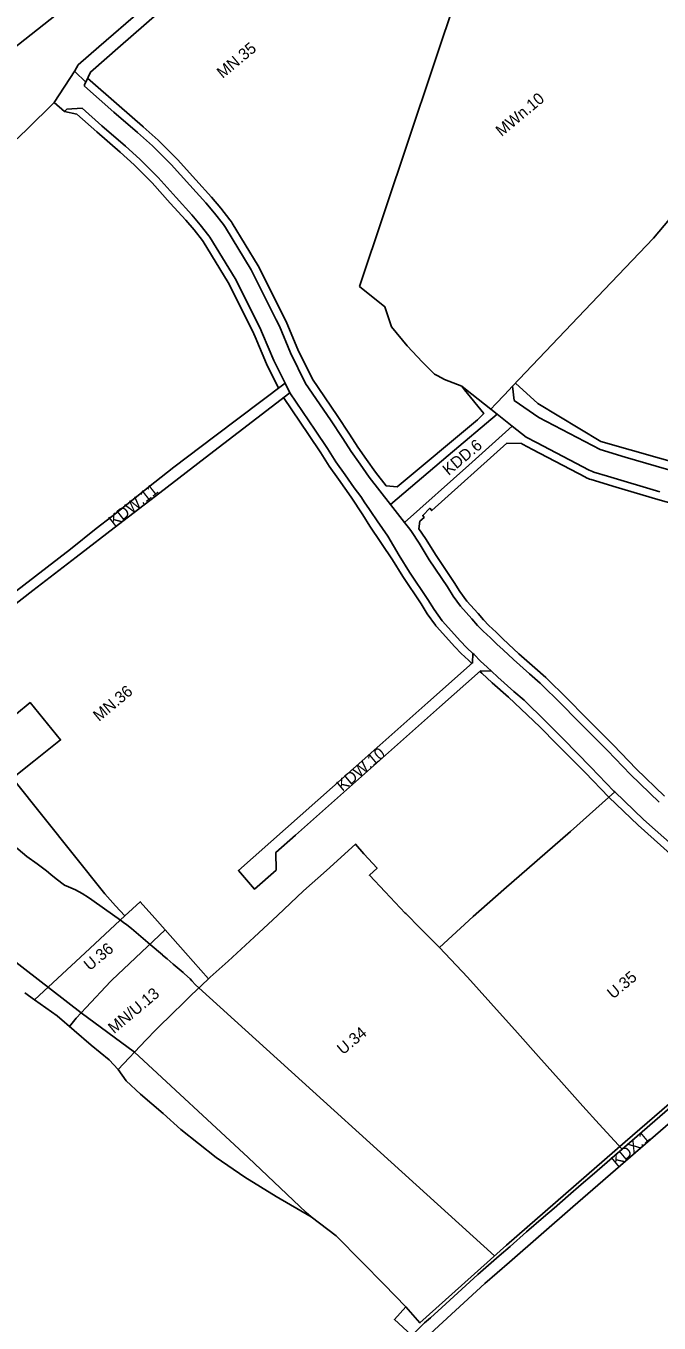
# Model space of a CAD drawing. Extents: x 7418616 to 7420822, y 5550745 to 5553106.
# Drawn here: x 7419277 to 7419553, y 5551619 to 5552185 of the extents above; entities that cross this region are included whole.
import ezdxf

# ---------------------------------------------------------------- set-up
doc = ezdxf.new("R2010")
doc.units = 0
for name, color, linetype in [('granica obszaru objętego planem', 7, 'Continuous'), ('granica strefy zwiększonej wysokości zabudowy', 7, 'Continuous'), ('linie rozgraniczające', 7, 'Continuous'), ('nieprzekraczalne linie zabudowy', 7, 'Continuous'), ('przeznaczenia terenów', 7, 'Continuous')]:
    doc.layers.add(name, color=color, linetype=linetype)

msp = doc.modelspace()

# ---------------------------------------------------------------- linework, layer by layer
at = {"layer": 'granica obszaru objętego planem'}
msp.add_lwpolyline([(7419449.2, 5551610.35), (7419437.9, 5551620.76), (7419442.91, 5551626.23), (7419433.45, 5551635.98), (7419423.64, 5551645.92), (7419412.45, 5551657.3), (7419401.59, 5551665.49), (7419386.37, 5551674.34), (7419372.7, 5551682.86), (7419360.17, 5551691.36), (7419344.8, 5551703.65), (7419337.04, 5551710.52), (7419327.19, 5551719.01), (7419320.85, 5551724.84), (7419317.35, 5551729.81), (7419313.4, 5551733.94), (7419305.54, 5551740.35), (7419290.8, 5551753.13), (7419285.81, 5551756.69), (7419280.87, 5551760.17), (7419276.65, 5551763.24)], dxfattribs=at)
at = {"layer": 'granica strefy zwiększonej wysokości zabudowy'}
for points in [[(7419269.08, 5551829.76), (7419277.58, 5551822.71), (7419282, 5551819.44), (7419282.05, 5551819.4), (7419284.9, 5551817.28), (7419285.5, 5551816.83), (7419286.11, 5551816.35), (7419288.07, 5551814.8), (7419290.39, 5551812.96), (7419293.92, 5551810.16), (7419295.78, 5551809.43), (7419298.76, 5551808.08), (7419301.65, 5551806.54), (7419304.43, 5551804.81), (7419305.93, 5551803.77), (7419311.44, 5551799.79), (7419318.36, 5551794.88), (7419319.73, 5551793.91), (7419321.24, 5551792.8), (7419323.15, 5551791.25), (7419331.29, 5551784.35), (7419336.75, 5551779.72), (7419336.78, 5551779.69), (7419338.71, 5551778.05), (7419341.46, 5551775.71), (7419345.78, 5551772.04), (7419346.37, 5551771.53), (7419348.76, 5551769.3), (7419349.53, 5551768.5), (7419351.2, 5551766.76), (7419352.58, 5551765.32)], [(7419352.6, 5551765.34), (7419481.58, 5551648.48)]]:
    msp.add_lwpolyline(points, dxfattribs=at)
at = {"layer": 'linie rozgraniczające'}
for p, q in [((7419289.46, 5552151.49), (7419298.49, 5552165.33)), ((7419298.49, 5552165.33), (7419298.49, 5552165.08)), ((7419298.49, 5552165.08), (7419303.22, 5552160.41)), ((7419392.25, 5552024.94), (7419390.21, 5552029.04)), ((7419480.03, 5552017.75), (7419471.68, 5552024.34)), ((7419482.73, 5552015.61), (7419480.03, 5552017.75)), ((7419489.32, 5552010.39), (7419482.73, 5552015.61)), ((7419436.19, 5551976.2), (7419442.37, 5551968.29))]:
    msp.add_line(p, q, dxfattribs=at)
for points in [[(7419365.97, 5552250.04), (7419312.1, 5552206.93), (7419296.89, 5552194.85), (7419293.29, 5552192.01), (7419273.97, 5552176.76), (7419270.76, 5552174.26), (7419254.96, 5552161.91), (7419239.68, 5552149.67), (7419236.93, 5552147.47)], [(7419471.68, 5552024.34), (7419469.73, 5552025.85), (7419467.37, 5552027.79), (7419459.79, 5552030.67), (7419456.81, 5552032.24), (7419455.37, 5552033), (7419450.17, 5552038.3), (7419443.52, 5552045.43), (7419436.66, 5552053.6), (7419433.69, 5552062.45), (7419422.76, 5552071.31), (7419476.4, 5552231.68)], [(7419298.49, 5552165.33), (7419299.92, 5552167.9), (7419308.97, 5552175.78), (7419327.07, 5552191.53), (7419345.17, 5552207.3), (7419367.41, 5552226.67), (7419372.62, 5552223.69), (7419353.06, 5552206.57), (7419336.88, 5552192.4), (7419334.25, 5552190.1), (7419318.45, 5552176.27), (7419305.31, 5552164.76), (7419303.22, 5552160.41)], [(7419489.5, 5552027.77), (7419532.5, 5552072.94), (7419550.98, 5552092.35), (7419557.99, 5552100.66), (7419563.48, 5552108.39), (7419565.89, 5552112.66), (7419568.3, 5552117.09), (7419571.58, 5552124.75), (7419588.49, 5552168.69), (7419594.7, 5552185.4), (7419598.11, 5552195.09), (7419599.69, 5552199.82), (7419601.92, 5552206.93), (7419603.31, 5552211.68), (7419604.21, 5552214.8), (7419606.15, 5552222.19)], [(7419303.22, 5552160.41), (7419302.74, 5552159.41), (7419302.72, 5552158.67), (7419315.57, 5552147.36), (7419325.89, 5552138.49), (7419332.37, 5552132.57), (7419340.5, 5552124.44), (7419348.62, 5552115.4), (7419355.63, 5552107.75), (7419359.42, 5552103.21), (7419363.36, 5552098.23), (7419363.9, 5552097.48), (7419364.23, 5552096.97), (7419375.39, 5552078.6), (7419386.4, 5552056.77), (7419387.74, 5552053.89), (7419392.54, 5552042.3), (7419399.15, 5552029.02), (7419410.07, 5552013.09), (7419415.42, 5552004.92), (7419419, 5551999.29), (7419422.94, 5551993.81), (7419426.86, 5551988.16), (7419436.19, 5551976.2)], [(7419238.99, 5552145.43), (7419260.69, 5552123.96), (7419263.29, 5552126.31), (7419277.6, 5552139.69), (7419289.46, 5552151.49)], [(7419390.21, 5552029.04), (7419385.26, 5552038.98), (7419380.42, 5552050.67), (7419379.15, 5552053.39), (7419368.39, 5552074.71), (7419357.39, 5552092.82), (7419356.96, 5552093.42), (7419353.16, 5552098.22), (7419349.53, 5552102.58), (7419342.69, 5552110.03), (7419334.81, 5552118.81), (7419326.8, 5552126.83), (7419320.55, 5552132.53), (7419310.32, 5552141.32), (7419301.61, 5552149), (7419295.06, 5552148.62), (7419293.97, 5552147.53), (7419289.46, 5552151.49)], [(7419200.17, 5551882.67), (7419214.91, 5551893.91), (7419222.45, 5551899.78), (7419230.97, 5551906.24), (7419240.24, 5551913.47), (7419271.1, 5551937.05), (7419296.59, 5551956.64), (7419307.85, 5551965.65), (7419314.56, 5551971.02), (7419333.41, 5551985.96), (7419341.61, 5551992.46), (7419359.62, 5552006.02), (7419390.21, 5552029.04)], [(7419392.25, 5552024.94), (7419355.37, 5551996.55), (7419335.6, 5551981.33), (7419317.5, 5551967.39), (7419299.12, 5551953.24), (7419280.13, 5551938.61), (7419261.43, 5551924.21), (7419242.4, 5551909.56), (7419223.6, 5551895.08), (7419204.9, 5551880.69)], [(7419472.13, 5551911.27), (7419469.48, 5551913.7), (7419466.63, 5551916.66), (7419464.13, 5551919.52), (7419461.44, 5551922.48), (7419458.95, 5551925.24), (7419458.74, 5551925.5), (7419455.2, 5551930.43), (7419452.54, 5551934.69), (7419444.53, 5551946.62), (7419440.05, 5551953.87), (7419435.04, 5551962.43), (7419430.47, 5551969.02), (7419427.59, 5551973.14), (7419426.76, 5551974.41), (7419424.95, 5551976.92), (7419423.25, 5551979.67), (7419420.41, 5551983.43), (7419416.41, 5551989.19), (7419412.36, 5551994.82), (7419408.7, 5552000.58), (7419403.42, 5552008.64), (7419392.25, 5552024.94)], [(7419480.03, 5552017.75), (7419482.18, 5552020.07), (7419485.97, 5552024.06), (7419489.5, 5552027.77)], [(7419489.5, 5552027.77), (7419490.15, 5552021.57), (7419500.93, 5552014.06), (7419527.68, 5552000.16), (7419538.61, 5551996.88), (7419556.58, 5551991.54), (7419573.63, 5551986.81), (7419587.72, 5551983.01), (7419590.08, 5551982.51)], [(7419436.19, 5551976.2), (7419461.43, 5551997.57), (7419482.73, 5552015.61)], [(7419442.37, 5551968.29), (7419470.33, 5551993.36), (7419489.32, 5552010.39)], [(7419553.71, 5551981.75), (7419530.83, 5551988.56), (7419524.89, 5551990.35), (7419524.41, 5551990.53), (7419522.87, 5551991.2), (7419499.89, 5552003.24), (7419495.42, 5552005.6), (7419489.32, 5552010.39)], [(7419442.37, 5551968.29), (7419444.6, 5551965.43), (7419445.34, 5551964.34), (7419448.69, 5551959.3), (7419453.15, 5551952.07), (7419461.06, 5551940.31), (7419463.59, 5551936.23), (7419466.76, 5551931.81), (7419471.77, 5551926.28), (7419474.22, 5551923.48), (7419476.64, 5551920.97), (7419479.86, 5551918.03), (7419482.6, 5551915.2), (7419485.31, 5551912.75), (7419489.89, 5551908.52), (7419496.8, 5551902.33), (7419501.49, 5551898.2), (7419510.98, 5551888.98), (7419517.4, 5551882.48), (7419530.93, 5551868.85), (7419540.95, 5551858.38), (7419553.46, 5551846.41)], [(7419480.24, 5551903.55), (7419475.46, 5551903.57), (7419457.63, 5551887.76), (7419436.68, 5551869.19), (7419415.73, 5551850.61), (7419394.77, 5551832.04), (7419386.2, 5551824.44), (7419386.32, 5551816.77), (7419376.91, 5551808.42), (7419375.11, 5551810.48), (7419369.85, 5551816.5), (7419390.43, 5551834.74), (7419410.96, 5551852.94), (7419431.58, 5551871.22), (7419452.54, 5551889.8), (7419472.04, 5551907.08), (7419472.13, 5551911.27)], [(7419480.24, 5551903.55), (7419478.41, 5551905.23), (7419475.44, 5551907.92), (7419472.69, 5551910.76), (7419472.13, 5551911.27)], [(7419534.03, 5551850.88), (7419533.73, 5551851.17), (7419523.66, 5551861.7), (7419511.49, 5551873.96), (7419503.86, 5551881.7), (7419494.47, 5551890.79), (7419490.05, 5551894.68), (7419483.05, 5551900.95), (7419480.24, 5551903.55)], [(7419213.04, 5551869.32), (7419226.26, 5551879.01), (7419232.46, 5551883.78), (7419233.36, 5551882.9), (7419247.56, 5551864.17), (7419258.46, 5551872.91), (7419265.33, 5551878.57), (7419267.03, 5551879.97), (7419278.98, 5551889.81), (7419292.23, 5551873.48), (7419280.64, 5551864.29), (7419271.31, 5551856.81), (7419311.51, 5551806.43), (7419316.29, 5551801.08), (7419320.36, 5551796.74)], [(7419457.55, 5551782.96), (7419472.35, 5551796.53), (7419485.69, 5551808.21), (7419514.83, 5551833.6), (7419534.03, 5551850.88)], [(7419623.53, 5551770), (7419619.37, 5551773.85), (7419615.55, 5551777.67), (7419609.66, 5551783.38), (7419598.83, 5551793.4), (7419589.26, 5551801.63), (7419576.19, 5551812.52), (7419571.18, 5551816.89), (7419560.52, 5551826.38), (7419546.59, 5551838.86), (7419534.03, 5551850.88)], [(7419356.86, 5551769.32), (7419357.56, 5551769.98), (7419365.32, 5551777.02), (7419376.72, 5551787.51), (7419378.74, 5551789.4), (7419386.89, 5551797), (7419398.3, 5551807.65), (7419408.24, 5551816.63), (7419420.89, 5551828.06), (7419424.63, 5551823.9), (7419430.36, 5551817.54), (7419427.02, 5551814.5), (7419433.9, 5551807.26), (7419442.68, 5551798.01), (7419442.91, 5551797.76), (7419449.2, 5551791.41), (7419457.55, 5551782.96)], [(7419320.36, 5551796.74), (7419327.06, 5551802.94), (7419333.39, 5551795.8), (7419337.97, 5551790.63)], [(7419320.36, 5551796.74), (7419303.01, 5551780.68), (7419280.87, 5551760.17)], [(7419337.97, 5551790.63), (7419314.65, 5551768.72), (7419314.11, 5551768.16), (7419303.44, 5551756.85), (7419299.1, 5551752.11), (7419296.16, 5551748.48)], [(7419337.97, 5551790.63), (7419346.77, 5551780.71), (7419356.86, 5551769.32)], [(7419457.55, 5551782.96), (7419469.78, 5551770.09), (7419480.06, 5551758.64), (7419491.62, 5551745.76), (7419500.82, 5551735.51), (7419510.87, 5551724.23), (7419520.2, 5551713.77), (7419527.27, 5551705.91), (7419537.25, 5551694.98)], [(7419317.35, 5551729.81), (7419329.49, 5551742.61), (7419333.94, 5551747.18), (7419334.94, 5551748.25), (7419340.76, 5551753.87), (7419345.84, 5551758.88), (7419349.7, 5551762.65), (7419351.15, 5551763.98), (7419356.86, 5551769.32)], [(7419449.2, 5551610.35), (7419452.46, 5551613.53), (7419453.31, 5551614.36), (7419455.41, 5551616.28), (7419477.43, 5551636.49), (7419488.09, 5551645.77), (7419515.75, 5551669.86), (7419570.49, 5551717.29), (7419589.38, 5551733.67), (7419610.42, 5551751.9), (7419613.77, 5551754.84), (7419627.2, 5551766.58)], [(7419537.25, 5551694.98), (7419543.78, 5551700.67), (7419561.5, 5551715.99), (7419568.41, 5551722.1), (7419623.53, 5551770)], [(7419449.2, 5551610.35), (7419437.9, 5551620.76), (7419442.91, 5551626.23), (7419433.45, 5551635.98), (7419423.64, 5551645.92), (7419412.45, 5551657.3), (7419401.59, 5551665.49), (7419386.37, 5551674.34), (7419372.7, 5551682.86), (7419360.17, 5551691.36), (7419344.8, 5551703.65), (7419337.04, 5551710.52), (7419327.19, 5551719.01), (7419320.85, 5551724.84), (7419317.35, 5551729.81), (7419313.4, 5551733.94), (7419305.54, 5551740.35), (7419290.8, 5551753.13), (7419285.81, 5551756.69), (7419280.87, 5551760.17), (7419276.65, 5551763.24)], [(7419537.25, 5551694.98), (7419524.25, 5551683.72), (7419519.48, 5551679.65), (7419513.7, 5551674.67), (7419507.7, 5551669.36), (7419503.04, 5551665.3), (7419495.61, 5551658.92), (7419488.4, 5551652.57), (7419483.64, 5551648.47), (7419474.37, 5551640.41), (7419458.68, 5551626.03), (7419453.73, 5551621.45), (7419451.05, 5551619.22), (7419445.5, 5551613.76)]]:
    msp.add_lwpolyline(points, dxfattribs=at)
at = {"layer": 'nieprzekraczalne linie zabudowy'}
for points in [[(7419304.06, 5552162.17), (7419317.87, 5552150), (7419328.04, 5552141.25), (7419328.19, 5552141.14), (7419328.36, 5552140.96), (7419334.81, 5552135.08), (7419343.26, 5552126.61), (7419351.21, 5552117.75), (7419358.09, 5552110.26), (7419362.15, 5552105.4), (7419366.17, 5552100.32), (7419366.78, 5552099.46), (7419367.19, 5552098.85), (7419378.45, 5552080.3), (7419389.56, 5552058.28), (7419390.95, 5552055.3), (7419395.73, 5552043.75), (7419402.17, 5552030.8), (7419412.97, 5552015.04), (7419418.36, 5552006.82), (7419421.9, 5552001.25), (7419425.8, 5551995.83), (7419429.68, 5551990.23), (7419434.29, 5551984.33), (7419439.17, 5551983.88), (7419474.13, 5552013.18), (7419476.91, 5552015.93), (7419468.56, 5552026.19), (7419467.37, 5552027.79)], [(7419293.96, 5552147.53), (7419299.29, 5552146.37), (7419308.02, 5552138.68), (7419318.23, 5552129.9), (7419324.36, 5552124.31), (7419332.26, 5552116.41), (7419340.1, 5552107.67), (7419346.91, 5552100.25), (7419350.5, 5552095.95), (7419354.17, 5552091.31), (7419354.47, 5552090.89), (7419365.33, 5552073), (7419376, 5552051.86), (7419377.22, 5552049.26), (7419382.07, 5552037.53), (7419387.36, 5552026.9)], [(7419490.76, 5552029.09), (7419500.54, 5552020.23), (7419528.06, 5552003.69), (7419591.03, 5551985.84)], [(7419389.46, 5552022.79), (7419400.51, 5552006.69), (7419405.76, 5551998.68), (7419409.45, 5551992.87), (7419413.56, 5551987.18), (7419418.99, 5551979.33), (7419424.12, 5551971.73), (7419427.23, 5551966.75), (7419437.11, 5551951.98), (7419441.58, 5551944.73), (7419449.6, 5551932.79), (7419452.23, 5551928.57), (7419455.79, 5551923.6), (7419456.03, 5551923.28), (7419456.39, 5551922.85), (7419461.51, 5551917.19), (7419464.28, 5551914.04), (7419467.06, 5551911.17), (7419470.25, 5551908.25), (7419471.69, 5551906.77)], [(7419555.84, 5551848.97), (7419543.42, 5551860.86), (7419533.5, 5551871.23), (7419521.22, 5551883.6), (7419513.42, 5551891.49), (7419503.93, 5551900.71), (7419499.13, 5551904.95), (7419492.25, 5551911.11), (7419487.68, 5551915.32), (7419485.03, 5551917.72), (7419482.33, 5551920.5), (7419479.09, 5551923.48), (7419476.8, 5551925.85), (7419474.41, 5551928.58), (7419469.49, 5551934.01), (7419466.5, 5551938.18), (7419464, 5551942.2), (7419456.1, 5551953.96), (7419451.54, 5551961.34), (7419448.63, 5551965.58), (7419449.02, 5551968.88), (7419450.89, 5551970.56), (7419450.26, 5551971.39), (7419453.36, 5551974.55), (7419454.23, 5551973.55), (7419486.99, 5552002.92), (7419493.31, 5552002.81), (7419493.78, 5552002.51), (7419498.25, 5552000.14), (7419521.25, 5551988.1), (7419521.47, 5551987.99), (7419523.07, 5551987.29), (7419523.82, 5551987.02), (7419534.67, 5551983.76), (7419552.87, 5551978.35), (7419569.98, 5551973.6)], [(7419442.91, 5551626.23), (7419449.02, 5551619.26), (7419486.85, 5551653.22), (7419538.64, 5551698.19), (7419561.02, 5551717.57), (7419619.62, 5551768.92), (7419611.64, 5551776.75), (7419607.25, 5551780.84), (7419596.5, 5551790.79), (7419587, 5551798.95), (7419573.92, 5551809.86), (7419568.88, 5551814.26), (7419558.18, 5551823.77), (7419544.25, 5551836.26), (7419531.42, 5551848.53), (7419521.15, 5551859.26), (7419508.99, 5551871.5), (7419501.37, 5551879.21), (7419487.71, 5551892.09), (7419480.65, 5551898.41), (7419476.05, 5551902.65), (7419475.24, 5551903.38)], [(7419174.91, 5551856.3), (7419183.56, 5551845.76), (7419192.76, 5551838.5), (7419208.5, 5551826.3), (7419212.74, 5551821.26), (7419213.84, 5551822.17), (7419216.31, 5551819.63), (7419217.54, 5551819.28), (7419237.72, 5551803.64), (7419301.27, 5551754.54), (7419324.5, 5551737.35), (7419374.12, 5551691.34), (7419399.48, 5551667.41), (7419401.59, 5551665.49)]]:
    msp.add_lwpolyline(points, dxfattribs=at)

# ---------------------------------------------------------------- texts
at = {"layer": 'przeznaczenia terenów'}
for s, rotation, p in [('MN.35', 39.8439, (7419363, 5552161.77)), ('MWn.10', 39.8439, (7419484.69, 5552136.44)), ('KDD.6', 39.8439, (7419461.54, 5551988.62)), ('KDW.11', 38.082, (7419315.67, 5551966.27)), ('MN.36', 39.8439, (7419309.05, 5551881.31)), ('KDW.10', 39.8439, (7419415.24, 5551850.82)), ('U.36', 39.8439, (7419304.98, 5551772.6)), ('U.35', 39.8439, (7419533.32, 5551760.26)), ('MN/U.13', 39.8439, (7419315.58, 5551745.17)), ('U.34', 39.8439, (7419415.48, 5551735.96)), ('KDX.1', 39.8439, (7419535.04, 5551687.08))]:
    msp.add_text(s, height=5, rotation=rotation, dxfattribs=at).set_placement(p)

doc.saveas('drawing.dxf')
